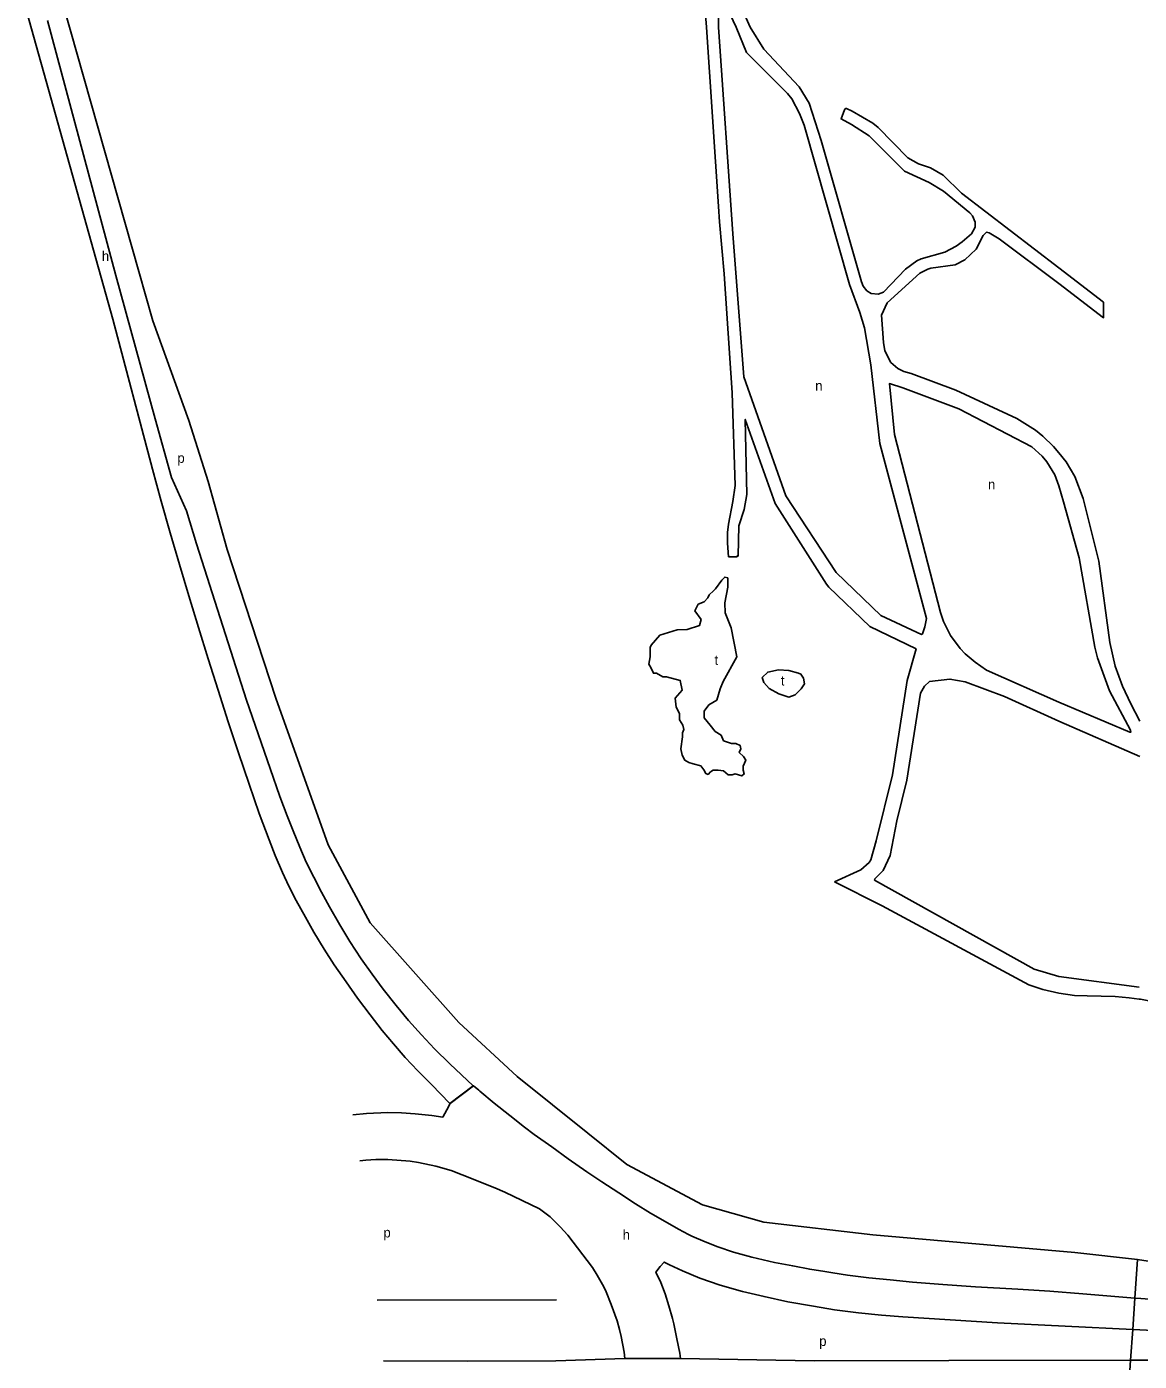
# Model space of a CAD drawing. Extents: x 162667 to 164645, y 379003 to 382150.
# Drawn here: x 162878 to 163333, y 379554 to 380100 of the extents above; entities that cross this region are included whole.
import ezdxf

# ---------------------------------------------------------------- set-up
doc = ezdxf.new("R2010")
doc.units = 0
for name, color, linetype in [('BLT_Basislijn', 7, 'Continuous'), ('BLT_Centroide', 7, 'Continuous'), ('BLT_Vlakafsluiter', 7, 'Continuous')]:
    doc.layers.add(name, color=color, linetype=linetype)

msp = doc.modelspace()

# ---------------------------------------------------------------- linework, layer by layer
at = {"layer": 'BLT_Basislijn'}
for p, q in [((162877.66, 380106.12), (162912.89, 379980.42)), ((162886.21, 380102.76), (162914.07, 379998.35)), ((162930.16, 379939.7), (162914.07, 379998.35)), ((162912.89, 379980.42), (162929.08, 379918.99)), ((163332.19, 379595.54), (163340.14, 379594.32)), ((163021.08, 379578.87), (163094.46, 379578.95)), ((163122.48, 379554.95), (163145.15, 379554.96))]:
    msp.add_line(p, q, dxfattribs=at)
for points in [[(163146.85, 380224.32), (163151.85, 380157.41), (163157.18, 380124.68), (163157.31, 380122.29), (163155.08, 380110.21), (163155.88, 380100), (163160.69, 380026.5), (163161.11, 380020.26)], [(162887.17, 380128.51), (162923.55, 380000), (162929.28, 379979.74), (162944.06, 379939)], [(163333.14, 379815.9), (163329.44, 379822.92), (163326.09, 379830.27), (163323.06, 379838.43), (163320.88, 379848.06), (163316.37, 379881.37), (163310, 379907.01), (163306.5, 379916.08), (163302.95, 379922.09), (163300, 379925.66), (163297.77, 379928.38), (163293.52, 379932.53), (163290.5, 379934.97), (163282.81, 379939.8), (163257.91, 379951.42), (163239.65, 379958.21), (163236.55, 379959.08), (163234.2, 379960.2), (163231.32, 379962.72), (163228.84, 379967.52), (163228.29, 379970.94), (163227.5, 379982.08), (163229.79, 379987.18), (163243.1, 379999.25), (163246.4, 380000.92), (163247.7, 380001.28), (163257.61, 380002.74), (163261.57, 380004.69), (163266.18, 380009.05), (163269.03, 380014.66), (163270.42, 380016.01), (163271.52, 380015.85), (163275.58, 380013.31), (163300, 379995.08), (163318.36, 379981.02), (163318.36, 379987.36), (163300, 380001.43), (163260.14, 380032.07), (163252.73, 380039.35), (163247.56, 380042.33), (163242.53, 380044.04), (163238.23, 380046.47), (163226.06, 380058.89), (163223.93, 380060.64), (163215.4, 380065.64), (163213.11, 380066.69), (163212.69, 380066.66), (163212.37, 380066.15), (163210.94, 380062.39), (163215.12, 380060.13), (163222.34, 380055.48), (163236.8, 380040.96), (163246.92, 380036.34), (163252.76, 380032.83), (163263.64, 380024.02), (163264.75, 380022.74), (163265.82, 380020.2), (163265.77, 380018.13), (163264.34, 380015.42), (163260.52, 380012.09), (163257.98, 380010.33), (163253.39, 380007.88), (163243.72, 380005.13), (163241.87, 380004.31), (163237.27, 380000.87), (163228.29, 379991.44), (163226.13, 379990.67), (163223.2, 379990.95), (163221.45, 379991.99), (163219.94, 379993.92), (163219.24, 379995.66), (163202.82, 380053.63), (163197.88, 380068.92), (163193.74, 380075.6), (163179.26, 380090.98), (163173.73, 380100), (163163.13, 380124.01)], [(163160.73, 380114.58), (163160.79, 380100), (163166.65, 380015.42), (163171.17, 379956.86), (163188.36, 379908.1), (163208.87, 379876.75), (163227.24, 379859.14), (163243.86, 379851.42), (163244.25, 379851.58), (163245.12, 379854.44), (163245.81, 379857.9), (163226.7, 379929.54), (163223.11, 379961.78), (163220.49, 379976.89), (163218.59, 379983.12), (163214.3, 379994.7), (163195.82, 380059.84), (163193.9, 380064.62), (163190.73, 380070.6), (163188.98, 380072.76), (163172.21, 380089.67), (163167.92, 380100), (163161.85, 380113.02), (163160.73, 380114.58)], [(163161.11, 380020.26), (163163.05, 379998.95), (163166.35, 379950.22), (163167.58, 379912.38), (163166.68, 379905.76), (163164.81, 379896.48), (163164.46, 379893.13), (163164.47, 379888.77), (163164.85, 379883.18), (163168.34, 379883.19), (163168.35, 379883.53), (163168.82, 379883.53), (163169.07, 379895.79), (163171.3, 379902.54), (163172.33, 379908.72), (163171.69, 379939.41), (163183.97, 379905.03), (163204.89, 379871.97), (163205.85, 379870.75), (163222.72, 379854.68), (163241.57, 379845.45), (163238.01, 379832.59), (163231.96, 379793.96), (163225.3, 379766.9), (163223.08, 379759.11), (163222.4, 379758.07), (163219.06, 379755.05), (163208.16, 379750.05)], [(163300, 379912.18), (163298.35, 379916.71), (163295.16, 379921.98), (163293.14, 379924.4), (163288.95, 379928.17), (163259.12, 379943.71), (163236.15, 379952.3), (163230.68, 379954.09), (163232.75, 379933.17), (163251.54, 379860.35), (163252.81, 379856.69), (163255.68, 379850.96), (163259.66, 379845.64), (163261.73, 379843.41), (163265.78, 379840), (163270.39, 379836.72), (163300, 379823.69), (163329.05, 379811.41), (163329.53, 379811.41), (163329.37, 379812.25), (163320.79, 379828.3), (163315.9, 379841.78), (163314.78, 379846.17), (163308.36, 379882.78), (163301.99, 379905.69), (163300, 379912.18)], [(163060.41, 379666.61), (163050.8, 379675.68), (163044.6, 379681.8), (163039.15, 379687.49), (163033.95, 379693.3), (163028.88, 379699.47), (163023.57, 379706.14), (163019.01, 379712.27), (163014.52, 379718.65), (163009.87, 379725.76), (163005.78, 379732.47), (163001.6, 379739.82), (162998.24, 379745.86), (162992.07, 379758.2), (162989.44, 379764.31), (162986.71, 379771.03), (162984.26, 379777.17), (162981.26, 379785.09), (162977.34, 379796.55), (162967.61, 379824.53), (162947.16, 379888.48), (162943.07, 379901.99), (162936.91, 379915.62), (162930.16, 379939.7)], [(163332.19, 379595.54), (163306.52, 379598.32), (163223.94, 379605.68), (163179.35, 379610.76), (163154.18, 379617.96), (163123.18, 379634.44), (163107.33, 379647.25), (163078.37, 379670.42), (163054.43, 379692.51), (163018.22, 379733.3), (163001.05, 379765.26), (162979.54, 379825.29), (162959.69, 379886.13), (162951.89, 379914.04), (162944.06, 379939)], [(162929.08, 379918.99), (162932.69, 379906), (162936.38, 379893.03), (162940.15, 379880.08), (162943.99, 379867.15), (162947.91, 379854.24), (162951.91, 379841.36), (162955.98, 379828.51), (162960.13, 379815.67), (162964.36, 379802.87), (162968.66, 379790.08), (162972.77, 379778.09)], [(163168.2, 379842.28), (163165.87, 379854.05), (163163.53, 379860.18), (163163.34, 379864.27), (163164.6, 379870.7), (163164.51, 379874.5), (163163.34, 379874.89), (163162.07, 379873.62), (163159.54, 379870.11), (163158.67, 379869.24), (163156.89, 379867.63), (163156.37, 379866.37), (163154.9, 379864.75), (163152.47, 379863.72), (163151.07, 379860.99), (163153.65, 379857.53), (163152.98, 379855.02), (163147.96, 379853.4), (163143.84, 379853.25), (163136.77, 379851.07), (163134.98, 379849.01), (163133.14, 379846.99), (163132.84, 379846.05), (163132.84, 379842.16), (163132.56, 379840.67), (163132.29, 379839.21), (163133.02, 379837.87), (163134.09, 379835.47), (163135.36, 379835.47), (163137.95, 379833.97), (163139.42, 379833.97), (163145.12, 379832.57), (163145.82, 379828.63), (163143.01, 379825.25), (163143.46, 379821.6), (163144.82, 379818.97), (163144.82, 379816.43), (163146.1, 379814.27), (163146.58, 379812.52), (163146.04, 379811.05), (163146.04, 379809.49), (163145.4, 379804.58), (163145.88, 379801.94), (163146.93, 379799.9), (163148.59, 379799.01), (163150.41, 379798.4), (163153.46, 379797.54), (163154.78, 379795.93), (163155.55, 379794.5), (163156.48, 379794.09), (163157.42, 379795.08), (163158.56, 379795.8), (163160.68, 379795.8), (163162.86, 379795.5), (163164.68, 379793.88), (163166.36, 379793.88), (163167.54, 379794.3), (163170.28, 379793.44), (163171.3, 379794.32), (163170.84, 379795.76), (163170.84, 379797.53), (163171.93, 379799.94), (163170.94, 379801.48), (163169.27, 379803.11), (163169.88, 379804.53), (163169.62, 379805.86), (163167.83, 379806.71), (163166, 379806.71), (163162.85, 379807.89), (163161.79, 379810.14), (163159.45, 379811.68), (163157.36, 379814.23), (163154.88, 379817.27), (163154.88, 379820.04), (163156.78, 379822.51), (163160.12, 379824.51), (163161.47, 379829.16), (163162.66, 379832.11), (163168.2, 379842.28)], [(163193.48, 379835.56), (163189.55, 379836.58), (163185.34, 379836.89), (163180.92, 379835.99), (163178.63, 379833.77), (163179.28, 379831.67), (163181.47, 379829.24), (163185.43, 379827.13), (163189.57, 379825.72), (163192.12, 379826.7), (163194.6, 379829.12), (163195.94, 379831.14), (163195.51, 379833.46), (163194.5, 379835.15), (163193.48, 379835.56)], [(163333.12, 379801.47), (163300, 379815.91), (163277.74, 379825.96), (163261.66, 379831.97), (163255.46, 379833.13), (163247.08, 379832.06), (163245.01, 379830.26), (163243.42, 379827.39), (163237.85, 379791.67), (163233.71, 379775.11), (163231, 379760.85), (163228.13, 379754.8), (163224.7, 379751.29), (163224.54, 379750.81), (163289.97, 379714.36), (163300, 379711.39), (163332.95, 379707.04)], [(162972.77, 379778.09), (162976.81, 379767.34), (162979.3, 379760.87), (162982.35, 379753.91), (162984.96, 379748.34), (162987.9, 379742.48), (162991.71, 379735.67), (162995.19, 379729.46), (162999.38, 379722.61), (163003.5, 379716.19), (163008.39, 379709.12), (163013.02, 379702.46), (163018.15, 379695.72), (163023.16, 379689.32), (163027.72, 379683.75), (163032.56, 379678.26), (163037.74, 379672.81), (163038.75, 379671.61), (163043.27, 379667.09), (163050.84, 379659.41)], [(163306.45, 379703.64), (163300, 379704.55), (163293.48, 379706.07), (163287.68, 379707.99), (163227.71, 379740.29), (163208.16, 379750.05)], [(163323.09, 379703.13), (163311.58, 379703.51), (163306.45, 379703.64)], [(163332.94, 379702.13), (163328.82, 379702.65), (163325.9, 379702.93), (163323.09, 379703.13)], [(163346.07, 379699.28), (163343.24, 379700.04), (163340.38, 379700.72), (163337.51, 379701.32), (163333.37, 379702.06), (163332.94, 379702.13)], [(163060.45, 379666.57), (163060.41, 379666.61)], [(163085.32, 379646.75), (163081.4, 379649.63), (163075.37, 379654.43), (163068.96, 379659.46), (163063.14, 379664.41), (163062.69, 379664.8), (163060.45, 379666.57)], [(163050.88, 379659.37), (163049.6, 379656.77), (163047.99, 379653.74)], [(163050.84, 379659.41), (163050.88, 379659.37)], [(163047.99, 379653.74), (163043.43, 379654.43), (163036.59, 379655.21), (163031.08, 379655.53), (163025.5, 379655.64), (163016.7, 379655.35), (163011.17, 379654.74)], [(163085.32, 379646.75), (163092.58, 379641.59), (163099.29, 379636.67), (163106.91, 379631.43), (163113.05, 379627.27), (163119.93, 379622.79), (163126.85, 379618.31), (163132.98, 379614.52), (163138.96, 379611.07)], [(163013.94, 379635.92), (163016.5, 379636.2), (163020.48, 379636.41), (163025.4, 379636.51), (163034.61, 379635.77), (163037.93, 379635.23), (163045.02, 379633.72), (163051.34, 379631.93), (163055.79, 379630.24), (163069.21, 379624.82), (163073.27, 379623.02), (163087.49, 379616.28), (163091.9, 379612.99), (163096.02, 379608.89), (163099.06, 379605.43), (163109.2, 379592.29), (163111.15, 379589.16), (163113.79, 379584.3), (163114.75, 379582.3), (163116.81, 379577.11), (163119.23, 379570.36), (163120.26, 379566.86), (163120.98, 379564.03), (163122.14, 379557.65), (163122.48, 379554.95)], [(163138.96, 379611.07), (163144.4, 379607.93), (163148.53, 379605.81), (163149.87, 379605.11), (163155.3, 379602.77), (163160.53, 379600.68), (163166.91, 379598.54), (163174.38, 379596.45), (163183.6, 379594.35), (163191.11, 379592.88), (163198.07, 379591.55), (163204.24, 379590.55), (163207.57, 379590.01), (163213.58, 379589.17), (163222.26, 379588.05), (163231.03, 379587.17), (163240.18, 379586.22), (163252.56, 379585.33), (163265.93, 379584.32), (163283.22, 379583.32), (163296.38, 379582.6), (163309.85, 379581.49), (163331.11, 379579.74)], [(163145.15, 379554.96), (163144.86, 379557.23), (163143.69, 379563.06), (163142.41, 379569.13), (163141.96, 379571.38), (163140.41, 379576.62), (163138.92, 379581.41), (163137.11, 379586.1), (163135.17, 379590.39), (163136.85, 379592.59), (163138.49, 379594.49), (163140.64, 379593.33), (163146.03, 379590.82), (163153.15, 379587.82), (163161.39, 379584.99), (163170.52, 379582.38), (163179.38, 379580.31), (163189.07, 379578.2), (163199.68, 379576.36), (163208.16, 379574.97), (163218.01, 379573.67), (163227.41, 379572.78), (163236.2, 379572.08), (163274.94, 379569.61), (163330.23, 379566.93)], [(163331.11, 379579.74), (163333.54, 379579.54), (163350, 379578.32)], [(163330.23, 379566.93), (163350, 379565.96)], [(163023.65, 379554), (163058.13, 379553.91), (163094.17, 379554.07), (163122.48, 379554.95)], [(163145.15, 379554.96), (163199.96, 379554.07), (163255.01, 379554.15), (163329.36, 379554.26)], [(163329.36, 379554.26), (163337.46, 379554.28), (163350, 379554.26)]]:
    msp.add_lwpolyline(points, dxfattribs=at)
at = {"layer": 'BLT_Vlakafsluiter'}
for p, q in [((163050.84, 379659.41), (163060.41, 379666.61)), ((163050.88, 379659.37), (163060.45, 379666.57)), ((163332.19, 379595.54), (163331.11, 379579.74)), ((163331.11, 379579.74), (163330.23, 379566.93)), ((163330.23, 379566.93), (163329.36, 379554.26)), ((163329.36, 379554.26), (163328.64, 379543.79))]:
    msp.add_line(p, q, dxfattribs=at)

# ---------------------------------------------------------------- texts
at = {"layer": 'BLT_Centroide'}
for s, p in [('h', (162908.43, 380004.26)), ('n', (163200.34, 379951.2)), ('p', (162939.33, 379921.63)), ('n', (163271.02, 379910.79)), ('t', (163159.14, 379838.96)), ('t', (163186.28, 379830.51)), ('p', (163023.64, 379604.56)), ('h', (163121.56, 379603.65)), ('p', (163201.97, 379560.13))]:
    msp.add_text(s, height=4, dxfattribs=at).set_placement(p)

doc.saveas('drawing.dxf')
